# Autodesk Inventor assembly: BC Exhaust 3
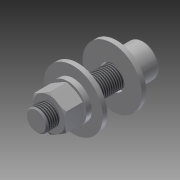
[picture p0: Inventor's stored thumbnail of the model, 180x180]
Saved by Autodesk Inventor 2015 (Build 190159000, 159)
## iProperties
Created: 2007-02
Part Number: BC Exhaust 3
Document SubType Name: Assembly
Designer: Autodesk, Inc.
Mass: 139.846 g
Surface Area: 109.169 cm^2
Volume: 17.7921 cm^3
Density: 7.86 g/cm^3
ClientObjectVersion: 1
Author: Autodesk, Inc.
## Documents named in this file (5)
- C:\Users\Public\Documents\Autodesk\Inventor 2015\Samples\Models\Assemblies\Blower\Blower\Design Accelerator\BC Exhaust 41.iam
- C:\Users\Public\Documents\Autodesk\Inventor 2015\Samples\Standard Parts\en-US\ANSI B18.22.1\ANSI B18.22.1 - 1_2 - wide - Type A.ipt
- C:\Users\Public\Documents\Autodesk\Inventor 2015\Samples\Standard Parts\en-US\ANSI B18.21.1\ANSI B18.21.1 - 0.5.ipt
- C:\Users\Public\Documents\Autodesk\Inventor 2015\Samples\Standard Parts\en-US\ANSI B18.3(13)\ANSI B18.3 - 1_2-20 UNF - 2(22).ipt
- C:\Users\Public\Documents\Autodesk\Inventor 2015\Samples\Standard Parts\en-US\ANSI B18.2.2(09)\ANSI B18.2.2 - 1_2 - 20(2).ipt
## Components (6 placed, 4 different names)
1. ANSI B18.22.1 - 1/2 - wide - Type A:1
2. ANSI B18.21.1 - 0.5:2
3. ANSI B18.3 - 1/2-20 UNF - 2:3
4. ANSI B18.22.1 - 1/2 - wide - Type A:4
5. ANSI B18.21.1 - 0.5:5
6. ANSI B18.2.2 - 1/2 - 20:6
